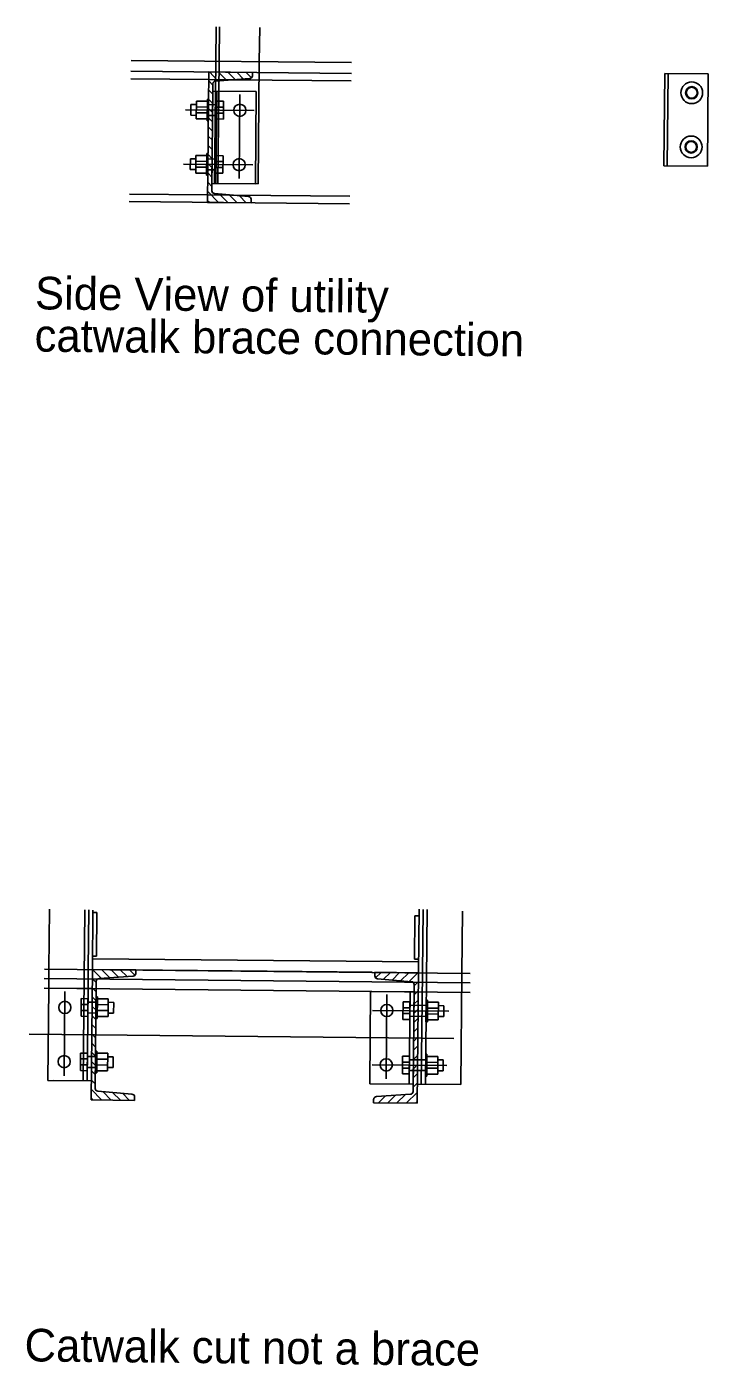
# Model space of a CAD drawing. Extents: x 632312 to 632425, y 378332 to 378413.
# Drawn here: x 632383.96 to 632389.18, y 378372.46 to 378382.73 of the extents above; entities that cross this region are included whole.
import ezdxf

# ---------------------------------------------------------------- set-up
doc = ezdxf.new("R2010")
doc.units = 0
for name, color, linetype in [('B_Boring', 7, 'Continuous'), ('R_Proposed Const Limits Cut', 7, 'Continuous'), ('R_Wall', 7, 'Continuous'), ('SHT_Dimensions', 7, 'Continuous'), ('USACE_Easement', 7, 'Continuous')]:
    doc.layers.add(name, color=color, linetype=linetype)

msp = doc.modelspace()

# ---------------------------------------------------------------- linework, layer by layer
at = {"layer": 'B_Boring'}
for p, q in [((632385.408, 378382.471), (632385.41, 378382.734)), ((632385.741, 378382.467), (632385.744, 378382.728)), ((632386.449, 378382.46), (632384.759, 378382.477)), ((632384.757, 378382.394), (632386.447, 378382.377)), ((632385.355, 378382.388), (632385.345, 378381.388)), ((632385.355, 378382.388), (632385.689, 378382.384)), ((632385.424, 378382.32), (632385.358, 378382.388)), ((632385.49, 378382.324), (632385.428, 378382.387)), ((632385.555, 378382.329), (632385.499, 378382.386)), ((632385.621, 378382.333), (632385.57, 378382.386)), ((632385.682, 378382.343), (632385.641, 378382.385)), ((632385.689, 378382.384), (632385.688, 378382.357)), ((632384.756, 378382.335), (632385.355, 378382.329)), ((632385.384, 378382.218), (632385.354, 378382.249)), ((632385.385, 378382.288), (632385.355, 378382.32)), ((632385.385, 378382.298), (632385.377, 378381.477)), ((632385.406, 378382.318), (632385.667, 378382.337)), ((632385.537, 378382.328), (632386.446, 378382.319)), ((632385.259, 378382.165), (632385.258, 378382.029)), ((632385.343, 378382.164), (632385.259, 378382.165)), ((632385.343, 378382.18), (632385.341, 378382.013)), ((632385.353, 378382.179), (632385.343, 378382.18)), ((632385.384, 378382.147), (632385.353, 378382.178)), ((632385.385, 378382.242), (632385.718, 378382.238)), ((632385.416, 378382.241), (632385.409, 378381.533)), ((632385.415, 378382.163), (632385.467, 378382.163)), ((632385.467, 378382.163), (632385.466, 378382.027)), ((632385.718, 378382.238), (632385.711, 378381.53)), ((632385.259, 378382.139), (632385.217, 378382.139)), ((632385.217, 378382.139), (632385.217, 378382.056)), ((632385.258, 378382.055), (632385.217, 378382.056)), ((632385.342, 378382.074), (632385.258, 378382.074)), ((632385.342, 378382.119), (632385.259, 378382.12)), ((632385.383, 378382.076), (632385.352, 378382.107)), ((632385.414, 378382.073), (632385.466, 378382.072)), ((632385.415, 378382.118), (632385.467, 378382.118)), ((632385.341, 378382.028), (632385.258, 378382.029)), ((632385.352, 378382.013), (632385.341, 378382.013)), ((632385.382, 378381.935), (632385.351, 378381.966)), ((632385.382, 378382.006), (632385.352, 378382.037)), ((632385.414, 378382.028), (632385.466, 378382.027)), ((632385.381, 378381.864), (632385.35, 378381.895)), ((632385.255, 378381.748), (632385.254, 378381.613)), ((632385.339, 378381.747), (632385.255, 378381.748)), ((632385.339, 378381.763), (632385.337, 378381.596)), ((632385.349, 378381.763), (632385.339, 378381.763)), ((632385.38, 378381.723), (632385.349, 378381.754)), ((632385.38, 378381.793), (632385.35, 378381.825)), ((632385.411, 378381.747), (632385.463, 378381.746)), ((632385.463, 378381.746), (632385.462, 378381.611)), ((632385.213, 378381.722), (632385.212, 378381.639)), ((632385.254, 378381.639), (632385.212, 378381.639)), ((632385.255, 378381.722), (632385.213, 378381.722)), ((632385.338, 378381.657), (632385.254, 378381.658)), ((632385.338, 378381.702), (632385.255, 378381.703)), ((632385.379, 378381.652), (632385.348, 378381.683)), ((632385.41, 378381.656), (632385.462, 378381.656)), ((632385.411, 378381.701), (632385.463, 378381.701)), ((632385.337, 378381.612), (632385.254, 378381.613)), ((632385.347, 378381.596), (632385.337, 378381.596)), ((632385.377, 378381.511), (632385.347, 378381.542)), ((632385.378, 378381.581), (632385.348, 378381.612)), ((632385.378, 378381.533), (632385.711, 378381.53)), ((632385.41, 378381.611), (632385.462, 378381.611)), ((632384.746, 378381.452), (632385.346, 378381.446)), ((632385.429, 378381.387), (632385.346, 378381.471)), ((632385.398, 378381.456), (632385.658, 378381.433)), ((632385.499, 378381.386), (632385.434, 378381.453)), ((632385.57, 378381.386), (632385.511, 378381.446)), ((632385.528, 378381.444), (632386.436, 378381.435)), ((632385.641, 378381.385), (632385.588, 378381.439)), ((632385.678, 378381.418), (632385.665, 378381.431)), ((632384.743, 378381.394), (632386.432, 378381.377)), ((632385.358, 378381.388), (632385.345, 378381.4)), ((632385.348, 378381.388), (632385.345, 378381.391)), ((632385.345, 378381.388), (632385.679, 378381.384)), ((632385.345, 378381.388), (632385.679, 378381.384)), ((632385.679, 378381.384), (632385.679, 378381.412)), ((632384.128, 378375.508), (632384.132, 378375.969)), ((632384.43, 378375.505), (632384.434, 378375.962)), ((632384.461, 378375.505), (632384.465, 378375.961)), ((632384.496, 378375.942), (632384.465, 378375.943)), ((632384.493, 378375.609), (632384.496, 378375.942)), ((632386.931, 378375.585), (632386.934, 378375.918)), ((632386.934, 378375.918), (632386.965, 378375.918)), ((632386.961, 378375.48), (632386.966, 378375.968)), ((632386.992, 378375.48), (632386.997, 378375.966)), ((632387.294, 378375.477), (632387.299, 378375.953)), ((632384.462, 378375.609), (632384.493, 378375.609)), ((632386.962, 378375.564), (632384.462, 378375.588)), ((632386.962, 378375.584), (632386.931, 378375.585)), ((632387.359, 378375.476), (632384.094, 378375.509)), ((632384.461, 378375.505), (632384.451, 378374.505)), ((632384.461, 378375.505), (632384.794, 378375.502)), ((632386.606, 378375.484), (632384.461, 378375.505)), ((632384.53, 378375.437), (632384.463, 378375.505)), ((632384.595, 378375.442), (632384.534, 378375.504)), ((632384.661, 378375.446), (632384.605, 378375.504)), ((632384.727, 378375.451), (632384.675, 378375.503)), ((632384.788, 378375.46), (632384.746, 378375.502)), ((632384.794, 378375.502), (632384.794, 378375.475)), ((632386.961, 378375.48), (632386.627, 378375.484)), ((632386.627, 378375.484), (632386.627, 378375.456)), ((632386.633, 378375.442), (632386.675, 378375.483)), ((632386.694, 378375.431), (632386.746, 378375.482)), ((632386.759, 378375.425), (632386.817, 378375.482)), ((632386.825, 378375.419), (632386.888, 378375.481)), ((632386.89, 378375.414), (632386.958, 378375.48)), ((632386.961, 378375.48), (632386.951, 378374.48)), ((632387.358, 378375.404), (632384.091, 378375.436)), ((632384.126, 378375.363), (632384.119, 378374.654)), ((632384.126, 378375.363), (632384.459, 378375.359)), ((632384.49, 378375.335), (632384.459, 378375.366)), ((632384.491, 378375.406), (632384.46, 378375.437)), ((632384.491, 378375.415), (632384.483, 378374.594)), ((632384.512, 378375.436), (632384.773, 378375.454)), ((632386.908, 378375.412), (632386.648, 378375.435)), ((632386.929, 378375.391), (632386.921, 378374.57)), ((632386.929, 378375.381), (632386.96, 378375.412)), ((632384.375, 378375.282), (632384.374, 378375.147)), ((632384.427, 378375.281), (632384.375, 378375.282)), ((632384.421, 378374.651), (632384.428, 378375.36)), ((632384.427, 378375.281), (632384.426, 378375.146)), ((632384.489, 378375.264), (632384.459, 378375.295)), ((632384.49, 378375.296), (632384.488, 378375.13)), ((632384.49, 378375.296), (632384.5, 378375.296)), ((632384.5, 378375.296), (632384.498, 378375.13)), ((632384.5, 378375.281), (632384.583, 378375.28)), ((632384.583, 378375.28), (632384.582, 378375.144)), ((632386.595, 378375.338), (632386.588, 378374.63)), ((632386.928, 378375.335), (632386.595, 378375.338)), ((632386.89, 378374.627), (632386.897, 378375.335)), ((632386.928, 378375.335), (632386.921, 378374.626)), ((632386.927, 378375.24), (632386.959, 378375.271)), ((632386.928, 378375.311), (632386.959, 378375.341)), ((632387.021, 378375.271), (632387.019, 378375.105)), ((632387.021, 378375.271), (632387.032, 378375.271)), ((632387.032, 378375.271), (632387.03, 378375.105)), ((632384.426, 378375.191), (632384.374, 378375.192)), ((632384.427, 378375.236), (632384.375, 378375.237)), ((632384.489, 378375.194), (632384.458, 378375.225)), ((632384.499, 378375.236), (632384.583, 378375.235)), ((632384.499, 378375.19), (632384.582, 378375.19)), ((632384.582, 378375.171), (632384.624, 378375.17)), ((632384.583, 378375.254), (632384.625, 378375.253)), ((632384.625, 378375.253), (632384.624, 378375.17)), ((632386.844, 378375.257), (632386.843, 378375.122)), ((632386.896, 378375.167), (632386.843, 378375.167)), ((632386.896, 378375.257), (632386.844, 378375.257)), ((632386.896, 378375.212), (632386.844, 378375.212)), ((632386.896, 378375.257), (632386.895, 378375.121)), ((632386.927, 378375.169), (632386.958, 378375.2)), ((632387.031, 378375.256), (632387.115, 378375.255)), ((632387.031, 378375.21), (632387.114, 378375.21)), ((632387.031, 378375.165), (632387.114, 378375.164)), ((632387.115, 378375.255), (632387.113, 378375.119)), ((632387.114, 378375.229), (632387.156, 378375.228)), ((632387.156, 378375.228), (632387.155, 378375.145)), ((632384.426, 378375.146), (632384.374, 378375.147)), ((632384.488, 378375.123), (632384.457, 378375.154)), ((632384.487, 378375.052), (632384.457, 378375.083)), ((632384.488, 378375.13), (632384.498, 378375.13)), ((632384.499, 378375.145), (632384.582, 378375.144)), ((632386.895, 378375.121), (632386.843, 378375.122)), ((632386.925, 378375.028), (632386.957, 378375.058)), ((632386.926, 378375.099), (632386.957, 378375.129)), ((632387.019, 378375.105), (632387.03, 378375.105)), ((632387.03, 378375.12), (632387.113, 378375.119)), ((632387.114, 378375.145), (632387.155, 378375.145)), ((632384.486, 378374.981), (632384.456, 378375.013)), ((632386.925, 378374.957), (632386.956, 378374.988)), ((632384.371, 378374.865), (632384.37, 378374.73)), ((632384.423, 378374.865), (632384.371, 378374.865)), ((632384.423, 378374.865), (632384.422, 378374.729)), ((632384.486, 378374.911), (632384.455, 378374.942)), ((632384.485, 378374.84), (632384.455, 378374.871)), ((632384.485, 378374.88), (632384.484, 378374.713)), ((632384.485, 378374.88), (632384.496, 378374.88)), ((632384.496, 378374.88), (632384.494, 378374.713)), ((632384.496, 378374.864), (632384.579, 378374.863)), ((632384.579, 378374.863), (632384.578, 378374.728)), ((632386.924, 378374.886), (632386.955, 378374.917)), ((632387.017, 378374.855), (632387.015, 378374.688)), ((632387.017, 378374.855), (632387.027, 378374.855)), ((632387.027, 378374.855), (632387.026, 378374.688)), ((632384.422, 378374.775), (632384.37, 378374.775)), ((632384.423, 378374.82), (632384.371, 378374.82)), ((632384.484, 378374.769), (632384.454, 378374.8)), ((632384.495, 378374.819), (632384.579, 378374.818)), ((632384.495, 378374.774), (632384.578, 378374.773)), ((632384.578, 378374.754), (632384.62, 378374.753)), ((632384.579, 378374.837), (632384.62, 378374.837)), ((632384.62, 378374.837), (632384.62, 378374.753)), ((632386.84, 378374.841), (632386.839, 378374.705)), ((632386.891, 378374.75), (632386.839, 378374.75)), ((632386.892, 378374.84), (632386.84, 378374.841)), ((632386.892, 378374.795), (632386.84, 378374.796)), ((632386.892, 378374.84), (632386.891, 378374.705)), ((632386.923, 378374.816), (632386.954, 378374.846)), ((632386.923, 378374.745), (632386.954, 378374.776)), ((632387.026, 378374.749), (632387.11, 378374.748)), ((632387.027, 378374.839), (632387.111, 378374.838)), ((632387.027, 378374.794), (632387.11, 378374.793)), ((632387.111, 378374.838), (632387.109, 378374.703)), ((632387.11, 378374.812), (632387.152, 378374.812)), ((632387.152, 378374.812), (632387.151, 378374.728)), ((632384.119, 378374.654), (632384.452, 378374.651)), ((632384.422, 378374.729), (632384.37, 378374.73)), ((632384.483, 378374.628), (632384.452, 378374.659)), ((632384.484, 378374.699), (632384.453, 378374.73)), ((632384.484, 378374.713), (632384.494, 378374.713)), ((632384.494, 378374.729), (632384.578, 378374.728)), ((632386.891, 378374.705), (632386.839, 378374.705)), ((632386.922, 378374.674), (632386.953, 378374.705)), ((632387.015, 378374.688), (632387.026, 378374.688)), ((632387.026, 378374.704), (632387.109, 378374.703)), ((632387.11, 378374.729), (632387.151, 378374.728)), ((632384.534, 378374.504), (632384.452, 378374.588)), ((632384.503, 378374.573), (632384.764, 378374.55)), ((632384.605, 378374.504), (632384.54, 378374.57)), ((632384.676, 378374.503), (632384.616, 378374.563)), ((632384.746, 378374.502), (632384.693, 378374.556)), ((632384.783, 378374.536), (632384.771, 378374.549)), ((632386.588, 378374.63), (632386.921, 378374.626)), ((632386.9, 378374.55), (632386.639, 378374.531)), ((632386.726, 378374.483), (632386.786, 378374.542)), ((632386.797, 378374.482), (632386.863, 378374.547)), ((632386.868, 378374.481), (632386.952, 378374.563)), ((632386.921, 378374.604), (632386.952, 378374.634)), ((632384.463, 378374.505), (632384.451, 378374.518)), ((632384.454, 378374.505), (632384.451, 378374.508)), ((632384.451, 378374.505), (632384.784, 378374.502)), ((632384.451, 378374.505), (632384.784, 378374.502)), ((632384.784, 378374.502), (632384.784, 378374.529)), ((632386.617, 378374.484), (632386.618, 378374.511)), ((632386.951, 378374.48), (632386.617, 378374.484)), ((632386.951, 378374.48), (632386.617, 378374.484)), ((632386.619, 378374.517), (632386.632, 378374.53)), ((632386.655, 378374.483), (632386.71, 378374.536)), ((632386.938, 378374.48), (632386.951, 378374.493)), ((632386.948, 378374.48), (632386.951, 378374.483))]:
    msp.add_line(p, q, dxfattribs=at)
for centre, radius in [((632389.057, 378382.229), 0.0833), ((632389.057, 378382.229), 0.0417), ((632385.592, 378382.094), 0.0469), ((632389.053, 378381.813), 0.0833), ((632389.053, 378381.813), 0.0417), ((632385.587, 378381.677), 0.0469), ((632384.25, 378375.215), 0.0469), ((632386.719, 378375.191), 0.0469), ((632384.245, 378374.799), 0.0469), ((632386.715, 378374.774), 0.0469)]:
    msp.add_circle(centre, radius, dxfattribs=at)
for centre, start, end in [((632385.667, 378382.358), 269.4304, 359.4388), ((632385.406, 378382.298), 89.4304, 179.4304), ((632385.398, 378381.477), 179.4304, 269.4304), ((632385.658, 378381.412), 359.4304, 89.4304), ((632384.773, 378375.475), 269.4304, 359.4388), ((632384.512, 378375.415), 89.4304, 179.4304), ((632386.648, 378375.456), 179.4219, 269.4304), ((632386.908, 378375.391), 359.4304, 89.4304), ((632384.503, 378374.594), 179.4304, 269.4304), ((632384.764, 378374.529), 359.4304, 89.4304), ((632386.9, 378374.57), 269.4304, 359.4304), ((632386.639, 378374.51), 89.4304, 179.4304)]:
    msp.add_arc(centre, 0.0208, start, end, dxfattribs=at)
at = {"layer": 'R_Proposed Const Limits Cut'}
for p, q in [((632385.434, 378382.47), (632385.436, 378382.734)), ((632385.398, 378381.533), (632385.408, 378382.471)), ((632385.424, 378381.533), (632385.434, 378382.47)), ((632385.741, 378382.467), (632385.732, 378381.53)), ((632388.843, 378381.669), (632388.85, 378382.377)), ((632389.184, 378382.374), (632388.85, 378382.377)), ((632388.876, 378382.377), (632388.869, 378381.669)), ((632389.177, 378381.666), (632389.184, 378382.374)), ((632385.355, 378382.329), (632385.537, 378382.328)), ((632385.414, 378382.054), (632385.352, 378382.054)), ((632385.415, 378382.137), (632385.353, 378382.138)), ((632385.41, 378381.637), (632385.348, 378381.638)), ((632385.411, 378381.72), (632385.349, 378381.721)), ((632389.177, 378381.666), (632388.843, 378381.669)), ((632385.732, 378381.53), (632385.398, 378381.533)), ((632385.528, 378381.444), (632385.346, 378381.446)), ((632384.39, 378374.652), (632384.403, 378375.963)), ((632387.015, 378374.625), (632387.028, 378375.965)), ((632384.128, 378375.508), (632384.126, 378375.357)), ((632384.43, 378375.505), (632384.428, 378375.36)), ((632386.992, 378375.48), (632386.983, 378374.626)), ((632387.294, 378375.477), (632387.286, 378374.623)), ((632387.357, 378375.33), (632384.091, 378375.363)), ((632384.426, 378375.172), (632384.488, 378375.171)), ((632384.427, 378375.255), (632384.489, 378375.255)), ((632386.896, 378375.231), (632387.021, 378375.23)), ((632386.895, 378375.148), (632387.02, 378375.146)), ((632384.422, 378374.755), (632384.484, 378374.755)), ((632384.423, 378374.839), (632384.485, 378374.838)), ((632386.892, 378374.814), (632387.017, 378374.813)), ((632386.891, 378374.731), (632387.016, 378374.73)), ((632387.286, 378374.623), (632386.952, 378374.626))]:
    msp.add_line(p, q, dxfattribs=at)
for centre in [(632389.057, 378382.229), (632389.053, 378381.813)]:
    msp.add_circle(centre, 0.0469, dxfattribs=at)
at = {"layer": 'R_Wall'}
for p, q in [((632385.593, 378382.216), (632385.586, 378381.571)), ((632385.702, 378382.093), (632385.174, 378382.098)), ((632385.692, 378381.676), (632385.161, 378381.681)), ((632384.251, 378375.338), (632384.244, 378374.69)), ((632386.72, 378375.314), (632386.713, 378374.666)), ((632386.609, 378375.192), (632387.195, 378375.186)), ((632383.975, 378375.01), (632387.233, 378374.977)), ((632386.606, 378374.775), (632387.179, 378374.77))]:
    msp.add_line(p, q, dxfattribs=at)
at = {"layer": 'SHT_Dimensions'}
for p, q in [((632385.385, 378382.242), (632385.378, 378381.533)), ((632384.161, 378374.654), (632384.452, 378374.651))]:
    msp.add_line(p, q, dxfattribs=at)

# ---------------------------------------------------------------- texts
at = {"layer": 'USACE_Easement'}
for s, p in [('Side View of utility ', (632384.02, 378380.568)), ('catwalk brace connection', (632384.017, 378380.244)), ('Catwalk cut not a brace', (632383.94, 378372.501))]:
    msp.add_text(s, height=0.25, rotation=359.4304, dxfattribs=at).set_placement(p)

doc.saveas('drawing.dxf')
